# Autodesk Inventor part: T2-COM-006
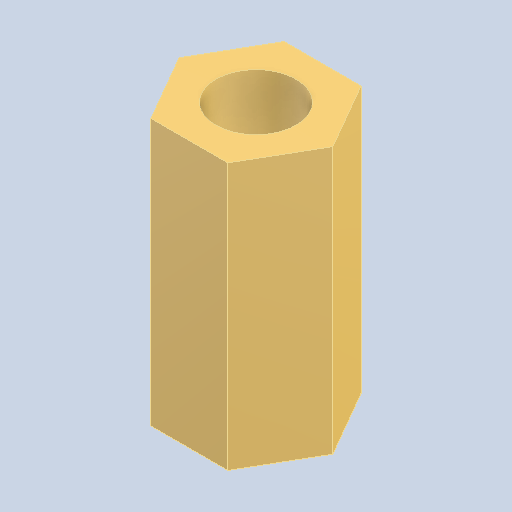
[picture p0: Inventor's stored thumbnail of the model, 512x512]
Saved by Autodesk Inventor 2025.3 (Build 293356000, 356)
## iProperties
Created: 2018-08
Part Number: T2-COM-006
Material: solidworks materials|Latón
Document SubType Name: Modeling
Designer: Luis MuÃ±oz
Density: 8.5 g/cm^3
Appearance: polished brass
Project: TESIS 2 - Plataforma mecatrÃ³nica preventiva desacoplada
Description: Separador roscado hembra-hembra M3 × 10 mm
Sending System: SolidWorks 2017
Last Author: Jonathan
Last Saved: 2018-08-15
Author: Luis M
Title: Separador roscado hembra-hembra M3 Ã— 10 mm
Revision Number: 00
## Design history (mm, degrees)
feature "Saliente-Extruir1"
node "Sólido1"
